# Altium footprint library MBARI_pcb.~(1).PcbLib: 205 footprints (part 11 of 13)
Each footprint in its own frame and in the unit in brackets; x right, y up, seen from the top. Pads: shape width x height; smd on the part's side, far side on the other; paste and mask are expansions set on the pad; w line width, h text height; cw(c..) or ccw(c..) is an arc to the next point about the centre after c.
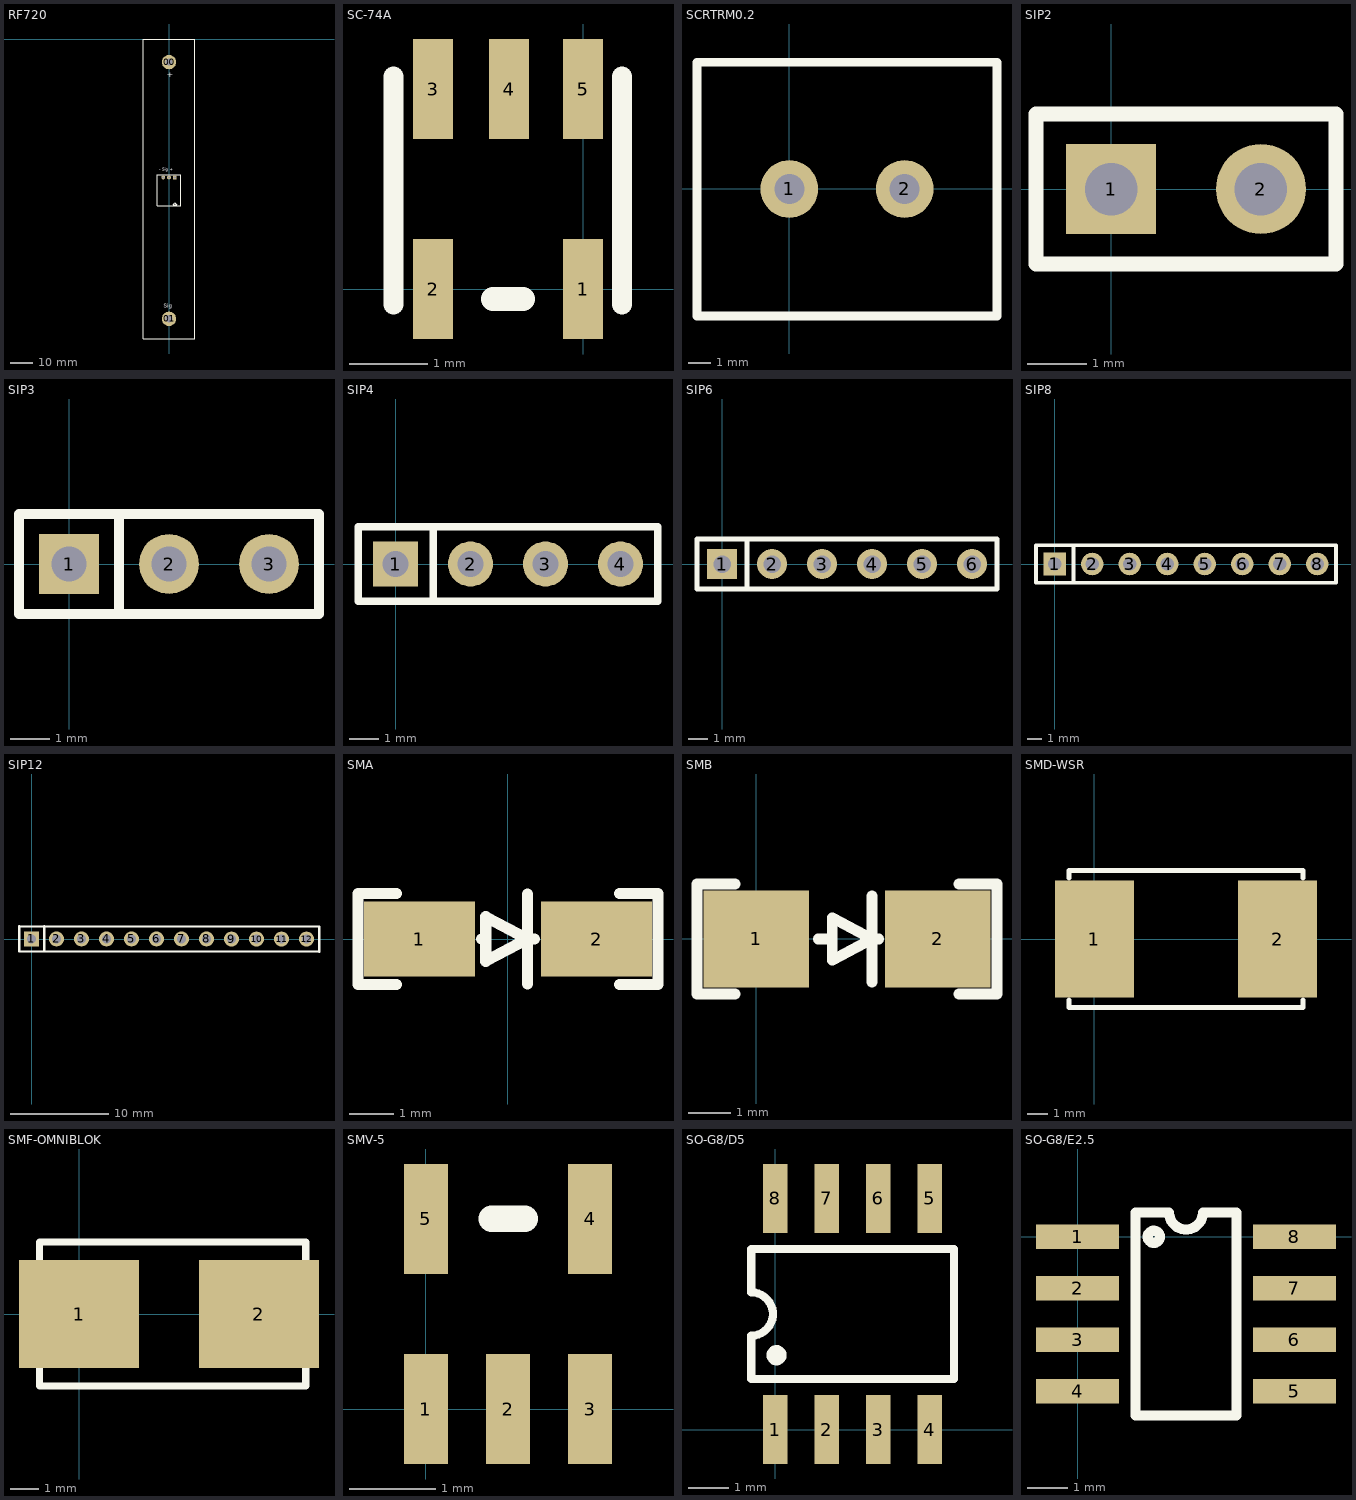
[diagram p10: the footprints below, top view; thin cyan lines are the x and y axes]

## RF720 [mil]
pads (5):
  round 250 hole 125: 00(0,-400) 01(0,-4850)
  rect 66x66 hole 42: 1(100,-2400)
  round 66 hole 42: 2(0,-2400) 3(-100,-2400)
TopOverlay:
  lines w10: -450,-5200 -450,-700 -450,0 450,0 450,-5200 -450,-5200 ; -200,-2890 -200,-2350 200,-2350 200,-2890 -200,-2890 ; 71.71,-2871.71 131.71,-2871.71 101.71,-2841.71 71.71,-2871.71
  text "- Sig +" at -170,-2280 h50
  text "+" at -40,-660 h100
  text "Sig" at -90,-4660 h70

## SC-74A [mil] "Mini5 - G1 Panasonic"
height 43.31
pads (5):
  rect 20x50 smd: 1(0,0) 2(-75,0) 3(-75,100) 4(-37,100) 5(0,100)
TopOverlay:
  lines w10: -94.69,-7.87 -94.69,106.3 ; 19.49,-7.87 19.49,106.3
  lines w12: -45,-5 -30,-5

## SCRTRM0.2 [mil]
pads (2):
  round 100 hole 52: 1(0,0) 2(200,0)
TopOverlay:
  lines w15: -160,-220 -160,220 0,220 200,220 360,220 360,-220 200,-220 0,-220 -160,-220

## SIP2 [mil]
pads (2):
  rect 60x60 hole 35: 1(0,0)
  round 60 hole 35: 2(100,0)
TopOverlay:
  lines w10: -50,-50 150,-50 150,50 -50,50 -50,-50

## SIP3 [mil]
pads (3):
  rect 60x60 hole 35: 1(0,0)
  round 60 hole 35: 2(100,0) 3(200,0)
TopOverlay:
  lines w10: 50,-50 50,50 ; -50,-50 -50,50 250,50 250,-50 -50,-50

## SIP4 [mil]
pads (4):
  rect 60x60 hole 35: 1(0,0)
  round 60 hole 35: 2(100,0) 3(200,0) 4(300,0)
TopOverlay:
  lines w10: 50,-50 50,50 ; -50,-50 350,-50 350,50 -50,50 -50,-50

## SIP6 [mil]
pads (6):
  rect 60x60 hole 35: 1(0,0)
  round 60 hole 35: 2(100,0) 3(200,0) 4(300,0) 5(400,0) 6(500,0)
TopOverlay:
  lines w10: 50,-50 50,50 ; -50,-50 -50,50 550,50 550,-50 -50,-50

## SIP8 [mil]
pads (8):
  rect 60x60 hole 35: 1(0,0.38)
  round 60 hole 35: 2(100,0.38) 3(200,0.38) 4(300,0.38) 5(400,0.38) 6(500,0.38) 7(600,0.38) 8(700,0.38)
TopOverlay:
  lines w10: 50,-49.62 50,50.38 ; -50,-49.62 -50,50.38 750,50.38 750,-49.62 -50,-49.62

## SIP12 [mil] "12 position SIP"
pads (12):
  rect 60x60 hole 35: 1(0,0.38)
  round 60 hole 35: 2(100,0.38) 3(200,0.38) 4(300,0.38) 5(400,0.38) 6(500,0.38) 7(600,0.38) 8(700,0.38) 9(800,0) 10(900,0) 11(1000,0) 12(1100,0)
TopOverlay:
  lines w10: 50,-49.62 50,50.38 ; -50,-49.62 -50,50.38 1150,50 1150,-50 -50,-49.62

## SMA [mm] "SMA Diode"
pads (2):
  rect 2.5x1.7 smd: 1(-2,0) 2(2,0)
TopOverlay:
  lines w0.254: -2.522,-1.024 -3.384,-1.024 -3.384,1.024 -2.522,1.024 ; -0.6,0 -0.576,0 ; 0.44,-1.016 0.44,1.016 ; 0.6,0 0.44,0 ; 2.522,-1.024 3.384,-1.024 3.384,1.024 2.522,1.024 ; 0.44,0 -0.5,-0.5 -0.5,0.5 0.44,0

## SMB [mm] "SMB Diode"
pads (2):
  rect 2.5x2.3 smd: 1(0,0) 2(4.3,0)
TopOverlay:
  lines w0.254: -0.5,-1.3 -1.4,-1.3 -1.4,1.3 -0.5,1.3 ; 1.47,0 1.724,0 ; 2.74,-1.016 2.74,1.016 ; 2.9,0 2.74,0 ; 4.8,-1.3 5.7,-1.3 5.7,1.3 4.8,1.3 ; 2.74,0 1.8,0.5 1.8,-0.5 2.74,0

## SMD-WSR [mil]
pads (2):
  rect 155x230 smd: 1(0,0) 2(360,0)
TopOverlay:
  lines w10: -50,-120 -50,-135 410,-135 410,-120 ; -50,120 -50,135 410,135 410,120

## SMF-OMNIBLOK [mil] "SMD Nano Fuse Holder"
height 150
pads (2):
  rect 167x150 smd: 1(0,0) 2(250,0)
TopOverlay:
  lines w10: -55,-75 -55,-100 315,-100 315,-75 ; -55,75 -55,100 315,100 315,75

## SMV-5 [mil]
pads (5):
  rect 20x50 smd: 1(0,0) 2(37.4,0) 3(74.8,0) 4(74.8,86.61) 5(0,86.61)
TopOverlay:
  lines w12: 30,86.61 45,86.61

## SO-G8/D5 [mm]
pads (8):
  rect 0.6x1.7 smd: 1(0,0) 2(1.27,0) 3(2.54,0) 4(3.81,0) 5(3.81,5.7) 6(2.54,5.7) 7(1.27,5.7) 8(0,5.7)
TopOverlay:
  circle w0.25: c0.027,1.834 r0.125
  lines w0.2: -0.595,2.317 ccw(c-0.595,2.85) -0.595,3.383 -0.595,4.45 4.405,4.45 4.405,1.25 -0.595,1.25 -0.595,2.317

## SO-G8/E2.5 [mm]
pads (8):
  rect 2.05x0.6 smd: 1(0,0) 2(0,-1.27) 3(0,-2.54) 4(0,-3.81) 5(5.35,-3.81) 6(5.35,-2.54) 7(5.35,-1.27) 8(5.35,0)
TopOverlay:
  circle w0.25: c1.882,0 r0.15
  lines w0.25: 2.258,0.595 1.425,0.595 1.425,-4.405 3.925,-4.405 3.925,0.595 3.092,0.595 cw(c2.675,0.595) 2.258,0.595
